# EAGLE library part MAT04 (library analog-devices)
Matched Monolithic Quad Transistor Source: http://www.analog.com/static/imported-files/data_sheets/MAT04.pdf
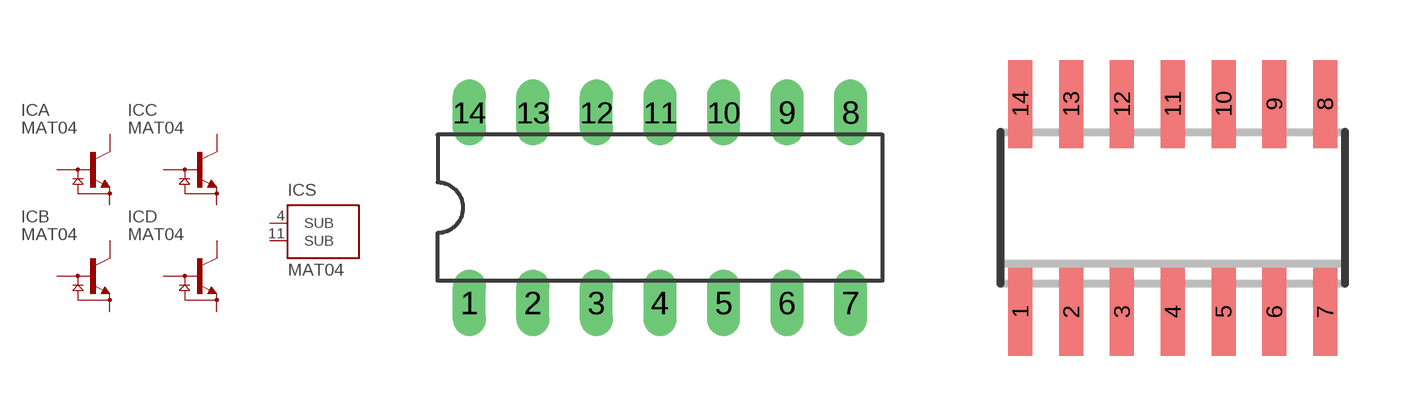
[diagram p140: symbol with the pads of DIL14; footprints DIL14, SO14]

Designator prefix IC; gates A=NPN+DIODE B=NPN+DIODE C=NPN+DIODE D=NPN+DIODE S=SUB

## MAT04P (OC_FARNELL: 1465698; OC_NEWARK: unknown)  [DIL14]
1  A:C  pas
2  A:B  pas
3  A:E  pas
4  S:SUB  pas
5  B:E  pas
6  B:B  pas
7  B:C  pas
8  C:C  pas
9  C:B  pas
10  C:E  pas
11  S:SUB  pas
12  D:E  pas
13  D:B  pas
14  D:C  pas

## MAT04S (MPN: MAT04FS; OC_FARNELL: unknown; OC_NEWARK: 66F5730)  [SO14]
Pads as for DIL14

## Footprint DIL14 (pad centres in mm)
Dual In Line Package
drill 0.813 long: 1 -7.62,-3.81; 2 -5.08,-3.81; 3 -2.54,-3.81; 4 0,-3.81; 5 2.54,-3.81; 6 5.08,-3.81; 7 7.62,-3.81; 8 7.62,3.81; 9 5.08,3.81; 10 2.54,3.81; 11 0,3.81; 12 -2.54,3.81; 13 -5.08,3.81; 14 -7.62,3.81

## Footprint SO14 (pad centres in mm)
14-Lead Narrow-Body SOIC (SO-14) Source: http://www.analog.com/static/imported-files/data_sheets/SSM2166.pdf
smd 0.6 x 2.2: 1 -3.81,-2.6; 2 -2.54,-2.6; 3 -1.27,-2.6; 4 0,-2.6; 5 1.27,-2.6; 6 2.54,-2.6; 7 3.81,-2.6; 8 3.81,2.6; 9 2.54,2.6; 10 1.27,2.6; 11 0,2.6; 12 -1.27,2.6; 13 -2.54,2.6; 14 -3.81,2.6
